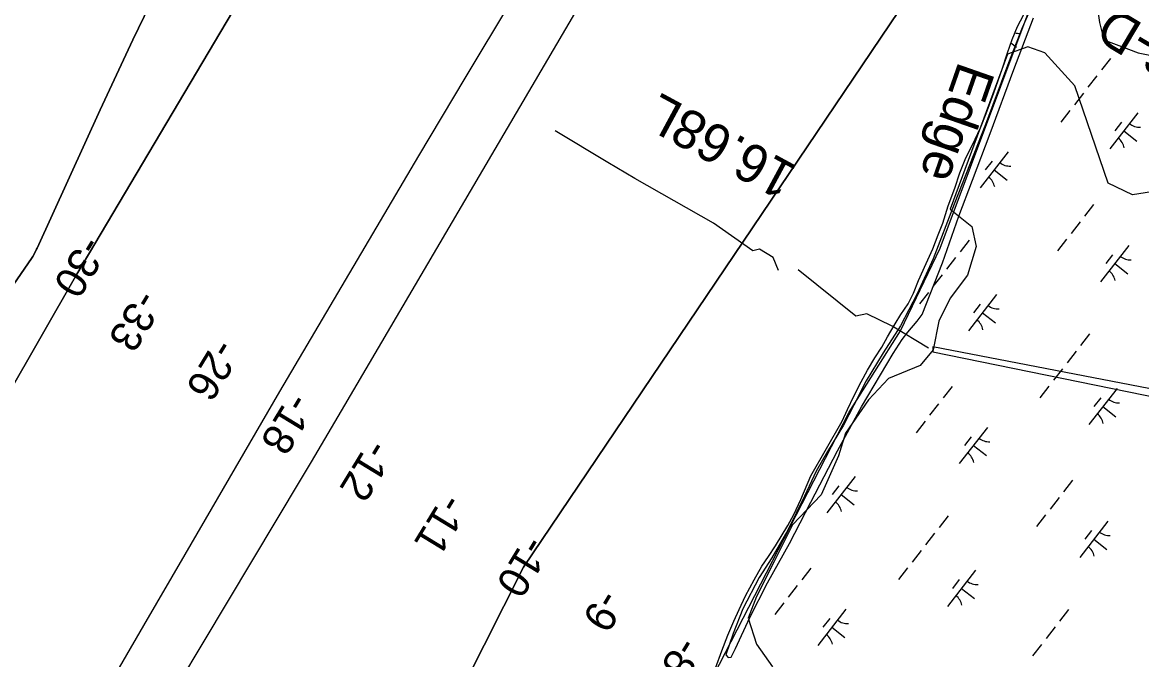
# Model space of a CAD drawing. Extents: x 3888273 to 3909528, y 158682 to 181032.
# Drawn here: x 3899572 to 3900792, y 167245 to 167939 of the extents above; entities that cross this region are included whole.
import ezdxf

# ---------------------------------------------------------------- set-up
doc = ezdxf.new("R2010")
doc.units = 0
for name, color, linetype in [('V-CHAN-DOCK', 7, 'Continuous'), ('V-LEVE-TOET', 7, 'Continuous'), ('V-RIVR-EDGE', 7, 'Continuous'), ('V-RIVR-IDEN', 7, 'Continuous'), ('V-RIVR-JETY', 7, 'Continuous'), ('V-RIVR-RANG', 7, 'Continuous'), ('V-RIVR-RANG-IDEN', 7, 'Continuous'), ('V-RRAP-FSHR', 7, 'Continuous'), ('V-STRM-FMON', 7, 'Continuous'), ('V-TOPO-DPTH', 7, 'Continuous'), ('V-TOPO-MINR', 7, 'Continuous'), ('V-WETL-SWMP', 7, 'Continuous')]:
    doc.layers.add(name, color=color, linetype=linetype)

msp = doc.modelspace()

# ---------------------------------------------------------------- linework, layer by layer
at = {"layer": 'V-CHAN-DOCK'}
msp.add_lwpolyline([(3900564.1, 167580.3), (3900918.3, 167508), (3900990.6, 167467.8), (3900997.5, 167477.5), (3900923.9, 167516.4), (3900564.1, 167585.8)], close=True, dxfattribs=at)
at = {"layer": 'V-LEVE-TOET'}
for points in [[(3900396, 167669), (3900390.1, 167683.2), (3900375.1, 167692.2), (3900367.9, 167690.4), (3900324.9, 167720.5), (3900239.4, 167769.3), (3900209.7, 167786.4), (3900152.6, 167821.2)], [(3900559.5, 167584.5), (3900519.7, 167608.3), (3900492.3, 167621.7), (3900480.3, 167619.3), (3900417.2, 167669.8)]]:
    msp.add_lwpolyline(points, dxfattribs=at)
at = {"layer": 'V-RIVR-EDGE'}
for points in [[(3900742.5, 167962.4), (3900745.6, 167938.9), (3900750.3, 167920.2), (3900787.8, 167906.1), (3900819.1, 167899.9)], [(3900811.3, 167756.1), (3900781.6, 167751.4), (3900755, 167763.9), (3900719, 167870.2), (3900686.2, 167906.1), (3900667.5, 167912.4), (3900645.6, 167904.6), (3900583.1, 167735.7), (3900606.5, 167717), (3900611.2, 167695.1), (3900601.8, 167663.8), (3900583.1, 167638.8), (3900570.6, 167613.8), (3900564.3, 167582.6), (3900550.2, 167565.4), (3900515.8, 167551.3), (3900494, 167527.9), (3900469, 167491.9), (3900461.1, 167466.9), (3900442.4, 167424.7), (3900411.1, 167391.9), (3900390.8, 167351.2), (3900372, 167313.7), (3900362.7, 167290.3), (3900372, 167262.1), (3900389.2, 167237.1)]]:
    msp.add_lwpolyline(points, dxfattribs=at)
at = {"layer": 'V-RIVR-JETY'}
for points in [[(3900678.9, 167973.2), (3900661.4, 167933.3), (3900646.5, 167895.2), (3900621.5, 167828.1), (3900587.3, 167741.2), (3900564.5, 167681.8), (3900546.8, 167643.6), (3900528.8, 167608.6), (3900509.9, 167579.1), (3900491.5, 167548.8), (3900477.8, 167522.3), (3900466.6, 167500.5), (3900449.1, 167471.8), (3900436.9, 167450.4), (3900424.2, 167423.2), (3900406, 167386), (3900388.7, 167356), (3900374.9, 167334.4), (3900357.1, 167300.3), (3900346.3, 167273.6), (3900338.5, 167250.4), (3900341, 167247.4), (3900344.2, 167247.8), (3900349, 167257.3), (3900364.6, 167291.1), (3900383.9, 167328.8), (3900407.8, 167371.7), (3900431.1, 167416.5), (3900460.2, 167472.4), (3900486.2, 167520.5), (3900521, 167578.4), (3900530.6, 167593.7), (3900536.7, 167601.7), (3900546.9, 167613.7), (3900552.5, 167620.9)], [(3900552.5, 167620.9), (3900574.6, 167677.3), (3900592.4, 167728), (3900607.4, 167767.5), (3900626.5, 167818.2), (3900652.2, 167887.9), (3900673.8, 167944.1)]]:
    msp.add_lwpolyline(points, dxfattribs=at)
at = {"layer": 'V-RRAP-FSHR'}
msp.add_lwpolyline([(3899996.7, 166588.8), (3900029.7, 166643.4), (3900051.8, 166695.8), (3900145, 166878), (3900473, 167514.6), (3900528.8, 167603.3), (3900571.9, 167693.2), (3900769.5, 168220.1), (3900854, 168410.1), (3901111.7, 168921.3), (3901230.8, 169130.1), (3901232.3, 169133), (3901298.6, 169231.8), (3901395, 169369.5), (3901586, 169601.1), (3901720.2, 169757.4), (3901855.1, 169965.2), (3902076, 170299.4), (3902258.6, 170576), (3902394.3, 170771.7), (3902466.4, 170877.4)], dxfattribs=at)
at = {"layer": 'V-TOPO-DPTH'}
for points in [[(3899237.6, 166978.5), (3899631, 167664.9), (3900022.2, 168324.2), (3900029.7, 168336.7), (3900037.2, 168349.1), (3900044.8, 168361.5), (3900052.5, 168373.8), (3900093.7, 168439.4), (3900122.1, 168484.4), (3900150.6, 168529.3), (3900179.4, 168574.1), (3900208.3, 168618.8), (3900453.3, 168995.5), (3900462.4, 169009.6), (3900471.5, 169023.7), (3900480.5, 169037.8), (3900489.5, 169051.9), (3900498.5, 169066.1), (3900507.4, 169080.2), (3900516.3, 169094.4), (3900525.2, 169108.6), (3900898, 169705.4)], [(3901523.7, 169550.8), (3901139.1, 169059.9), (3900979.7, 168809.1), (3900964.5, 168784.3), (3900949.7, 168759.3), (3900935.7, 168733.8), (3900922.2, 168708), (3900577.1, 168026.2), (3900117.9, 167345.7), (3899775.5, 166667.7), (3899771.7, 166626.4)], [(3900523.2, 169023), (3900524.6, 169025.3), (3900491.3, 169054.7), (3900490, 169052.7), (3900489.5, 169051.9), (3900480.5, 169037.8), (3900471.5, 169023.7), (3900462.4, 169009.6), (3900453.3, 168995.5), (3900208.3, 168618.8), (3900179.4, 168574.1), (3900150.6, 168529.3), (3900122.1, 168484.4), (3900093.7, 168439.4), (3900052.5, 168373.8), (3900044.8, 168361.5), (3900037.2, 168349.1), (3900029.7, 168336.7), (3900022.2, 168324.2), (3899631, 167664.9), (3899237.6, 166978.5), (3899234.6, 166973.7), (3899231.7, 166968.9), (3898895.1, 166384.7)], [(3899728.7, 167995.9), (3899692.2, 167920.1), (3899656.5, 167843.9), (3899587.8, 167693.4), (3899587.2, 167692), (3899585.4, 167688.1), (3899583.3, 167684.2), (3899582.5, 167683), (3899363.4, 167365)], [(3899363.4, 167365), (3899582.5, 167683), (3899583.3, 167684.2), (3899585.4, 167688.1), (3899587.2, 167692), (3899587.8, 167693.4), (3899656.5, 167843.9), (3899692.2, 167920.1), (3899728.7, 167995.9)], [(3899569, 167049.4), (3899614, 167127), (3899658.9, 167204.6), (3899704, 167282.1), (3899749, 167359.7), (3899826.1, 167492.2), (3899832.6, 167503.5), (3899839.2, 167514.7), (3899845.8, 167525.9), (3899852.4, 167537.1), (3899953.6, 167708.8), (3900003.9, 167793.7), (3900054.5, 167878.4), (3900105.3, 167962.9)], [(3899569, 167049.4), (3899614, 167127), (3899658.9, 167204.6), (3899704, 167282.1), (3899749, 167359.7), (3899826.1, 167492.2), (3899832.6, 167503.5), (3899839.2, 167514.7), (3899845.8, 167525.9), (3899852.4, 167537.1), (3899953.6, 167708.8), (3900003.9, 167793.7), (3900054.5, 167878.4), (3900105.3, 167962.9)]]:
    msp.add_lwpolyline(points, dxfattribs=at)
at = {"layer": 'V-TOPO-MINR'}
for points in [[(3899237.6, 166978.5), (3899631, 167664.9), (3900022.2, 168324.2), (3900029.7, 168336.7), (3900037.2, 168349.1), (3900044.8, 168361.5), (3900052.5, 168373.8), (3900093.7, 168439.4), (3900122.1, 168484.4), (3900150.6, 168529.3), (3900179.4, 168574.1), (3900208.3, 168618.8), (3900453.3, 168995.5), (3900462.4, 169009.6), (3900471.5, 169023.7), (3900480.5, 169037.8), (3900489.5, 169051.9), (3900498.5, 169066.1), (3900507.4, 169080.2), (3900516.3, 169094.4), (3900525.2, 169108.6), (3900898, 169705.4)], [(3899771.7, 166626.4), (3899775.5, 166667.7), (3900117.9, 167345.7), (3900577.1, 168026.2), (3900922.2, 168708), (3900935.7, 168733.8), (3900949.7, 168759.3), (3900964.5, 168784.3), (3900979.7, 168809.1), (3901139.1, 169059.9), (3901523.7, 169550.8)], [(3899571, 166932.8), (3899592.3, 166968.6), (3899613.6, 167004.4), (3899635, 167040.2), (3899876, 167442.3), (3899887, 167460.7), (3899897.9, 167479.1), (3899908.8, 167497.5), (3899919.7, 167516), (3900204.3, 168001.3)], [(3899363.4, 167365), (3899582.5, 167683), (3899583.3, 167684.2), (3899585.4, 167688.1), (3899587.2, 167692), (3899587.8, 167693.4), (3899656.5, 167843.9), (3899692.2, 167920.1), (3899728.7, 167995.9)], [(3899569, 167049.4), (3899614, 167127), (3899658.9, 167204.6), (3899704, 167282.1), (3899749, 167359.7), (3899826.1, 167492.2), (3899832.6, 167503.5), (3899839.2, 167514.7), (3899845.8, 167525.9), (3899852.4, 167537.1), (3899953.6, 167708.8), (3900003.9, 167793.7), (3900054.5, 167878.4), (3900105.3, 167962.9)]]:
    msp.add_lwpolyline(points, dxfattribs=at)
at = {"layer": 'V-WETL-SWMP'}
for p, q in [((3900656.4, 167934.6), (3900666.6, 167953.9)), ((3900650.5, 167920.7), (3900656.4, 167934.6)), ((3900645.3, 167906), (3900650.5, 167920.7)), ((3900649.1, 167916.8), (3900655.2, 167912.1)), ((3900639.7, 167888.3), (3900645.3, 167906)), ((3900757.7, 167900), (3900747.8, 167887.4)), ((3900635.3, 167876), (3900639.7, 167888.3)), ((3900742.9, 167881.1), (3900733.1, 167868.5)), ((3900630.5, 167862.5), (3900635.3, 167876)), ((3900622.3, 167840.1), (3900630.5, 167862.5)), ((3900728.2, 167862.1), (3900718.4, 167849.5)), ((3900713.4, 167843.2), (3900703.6, 167830.6)), ((3900616, 167824.3), (3900622.3, 167840.1)), ((3900787.6, 167840.7), (3900756.9, 167801.3)), ((3900607.4, 167805.8), (3900616, 167824.3)), ((3900769.8, 167830.5), (3900762.5, 167821)), ((3900772.2, 167821), (3900786.4, 167809.9)), ((3900600.2, 167791.8), (3900607.4, 167805.8)), ((3900646.3, 167798.3), (3900615.6, 167758.8)), ((3900593.5, 167775.3), (3900600.2, 167791.8)), ((3900628.6, 167788), (3900621.2, 167778.5)), ((3900588, 167758.7), (3900593.5, 167775.3)), ((3900631, 167778.5), (3900645.2, 167767.5)), ((3900580.9, 167739.4), (3900588, 167758.7)), ((3900575, 167720.5), (3900580.9, 167739.4)), ((3900739.3, 167740.8), (3900729.4, 167728.2)), ((3900724.5, 167721.9), (3900714.7, 167709.2)), ((3900569.8, 167707.8), (3900575, 167720.5)), ((3900563.9, 167692.4), (3900569.8, 167707.8)), ((3900603.5, 167702), (3900593.7, 167689.3)), ((3900709.8, 167702.9), (3900700, 167690.3)), ((3900556.8, 167676.6), (3900563.9, 167692.4)), ((3900777.6, 167696.1), (3900746.9, 167656.7)), ((3900759.9, 167685.9), (3900752.5, 167676.4)), ((3900548.6, 167658), (3900556.8, 167676.6)), ((3900588.8, 167683), (3900579, 167670.4)), ((3900762.3, 167676.4), (3900776.5, 167665.3)), ((3900574.1, 167664.1), (3900564.2, 167651.4)), ((3900543, 167644.1), (3900548.6, 167658)), ((3900537, 167632.6), (3900543, 167644.1)), ((3900559.3, 167645.1), (3900549.5, 167632.5)), ((3900633.5, 167642.7), (3900602.8, 167603.2)), ((3900529.1, 167620.9), (3900537, 167632.6)), ((3900615.7, 167632.4), (3900608.4, 167622.9)), ((3900523.1, 167610.9), (3900529.1, 167620.9)), ((3900618.1, 167622.9), (3900632.3, 167611.9)), ((3900514.8, 167596.6), (3900523.1, 167610.9)), ((3900734.8, 167599.8), (3900725, 167587.2)), ((3900508.4, 167585.4), (3900514.8, 167596.6)), ((3900500.9, 167573.8), (3900508.4, 167585.4)), ((3900720.1, 167580.9), (3900710.3, 167568.2)), ((3900493, 167560.2), (3900500.9, 167573.8)), ((3900485.8, 167547.5), (3900493, 167560.2)), ((3900705.4, 167561.9), (3900695.5, 167549.3)), ((3900478, 167532), (3900485.8, 167547.5)), ((3900585.2, 167542.7), (3900575.3, 167530.1)), ((3900690.6, 167543), (3900680.8, 167530.4)), ((3900764.8, 167540.5), (3900734.1, 167501.1)), ((3900470.9, 167517.4), (3900478, 167532)), ((3900747, 167530.3), (3900739.6, 167520.8)), ((3900465.3, 167505), (3900470.9, 167517.4)), ((3900570.4, 167523.8), (3900560.6, 167511.2)), ((3900749.4, 167520.8), (3900763.6, 167509.7)), ((3900431.1, 167445.1), (3900465.3, 167505)), ((3900555.7, 167504.9), (3900545.9, 167492.2)), ((3900623.5, 167498.1), (3900592.8, 167458.6)), ((3900605.8, 167487.8), (3900598.4, 167478.3)), ((3900608.2, 167478.3), (3900622.4, 167467.3)), ((3900420.3, 167419.6), (3900431.1, 167445.1)), ((3900479.4, 167444.6), (3900448.7, 167405.1)), ((3900716.4, 167440.6), (3900706.6, 167428)), ((3900461.6, 167434.3), (3900454.2, 167424.9)), ((3900412.4, 167403), (3900420.3, 167419.6)), ((3900464, 167424.9), (3900478.2, 167413.8)), ((3900701.7, 167421.7), (3900691.9, 167409)), ((3900406, 167391.1), (3900412.4, 167403)), ((3900580.7, 167401.8), (3900570.9, 167389.1)), ((3900687, 167402.7), (3900677.1, 167390.1)), ((3900754.8, 167395.9), (3900724.1, 167356.5)), ((3900392.5, 167369), (3900406, 167391.1)), ((3900566, 167382.8), (3900556.2, 167370.2)), ((3900737, 167385.7), (3900729.7, 167376.2)), ((3900385, 167357.4), (3900392.5, 167369)), ((3900739.4, 167376.2), (3900753.7, 167365.1)), ((3900377.8, 167346.9), (3900385, 167357.4)), ((3900551.2, 167363.9), (3900541.4, 167351.2)), ((3900369.2, 167331.9), (3900377.8, 167346.9)), ((3900431, 167344.7), (3900421.2, 167332.1)), ((3900536.5, 167344.9), (3900526.7, 167332.3)), ((3900359.8, 167314.5), (3900369.2, 167331.9)), ((3900610.7, 167342.5), (3900579.9, 167303)), ((3900592.9, 167332.2), (3900585.5, 167322.7)), ((3900416.3, 167325.7), (3900406.5, 167313.1)), ((3900595.3, 167322.7), (3900609.5, 167311.7)), ((3900353.1, 167299.8), (3900359.8, 167314.5)), ((3900401.6, 167306.8), (3900391.7, 167294.2)), ((3900347.1, 167287.1), (3900353.1, 167299.8)), ((3900469.4, 167300), (3900438.7, 167260.5)), ((3900712, 167299.6), (3900702.2, 167287)), ((3900340.7, 167271.6), (3900347.1, 167287.1)), ((3900451.7, 167289.7), (3900444.3, 167280.3)), ((3900334, 167254.7), (3900340.7, 167271.6)), ((3900454.1, 167280.3), (3900468.3, 167269.2)), ((3900697.3, 167280.7), (3900687.4, 167268)), ((3900682.5, 167261.7), (3900672.7, 167249.1)), ((3900327, 167235.8), (3900334, 167254.7))]:
    msp.add_line(p, q, dxfattribs=at)
for centre, start, end in [((3900658.1, 167944.8), 254.9283, 272.8866), ((3900789.4, 167842.6), 231.343, 272.8866), ((3900755.5, 167799), 11.343, 52.8866), ((3900648.1, 167800.2), 231.343, 272.8866), ((3900614.2, 167756.6), 11.343, 52.8866), ((3900779.4, 167698.1), 231.343, 272.8866), ((3900745.5, 167654.5), 11.343, 52.8866), ((3900635.3, 167644.6), 231.343, 272.8866), ((3900601.4, 167601), 11.343, 52.8866), ((3900766.6, 167542.4), 231.343, 272.8866), ((3900732.6, 167498.8), 11.343, 52.8866), ((3900625.3, 167500), 231.343, 272.8866), ((3900591.4, 167456.4), 11.343, 52.8866), ((3900481.2, 167446.5), 231.343, 272.8866), ((3900447.2, 167402.9), 11.343, 52.8866), ((3900756.6, 167397.8), 231.343, 272.8866), ((3900722.7, 167354.2), 11.343, 52.8866), ((3900612.4, 167344.4), 231.343, 272.8866), ((3900578.5, 167300.8), 11.343, 52.8866), ((3900471.2, 167301.9), 231.343, 272.8866), ((3900437.3, 167258.3), 11.343, 52.8866)]:
    msp.add_arc(centre, 17.6, start, end, dxfattribs=at)

# ---------------------------------------------------------------- texts
at = {"layer": 'V-RIVR-IDEN'}
msp.add_text('Edge', height=42, rotation=250.7537, dxfattribs=at).set_placement((3900592.6, 167898))
at = {"layer": 'V-RIVR-RANG'}
for s, rotation, p in [('-30', 238.7803, (3899638.1, 167709)), ('-33', 238.6383, (3899698.2, 167650)), ('-26', 238.6383, (3899782.8, 167596.6)), ('-18', 238.6383, (3899864, 167537.8)), ('-12', 238.6383, (3899950.1, 167486.8)), ('-11', 238.6383, (3900031.3, 167427.9)), ('-10', 238.6383, (3900120.7, 167382.4)), ('-9', 238.6383, (3900201.9, 167323.6)), ('-8', 238.6383, (3900287.7, 167272.1))]:
    msp.add_text(s, height=33.5, rotation=rotation, dxfattribs=at).set_placement(p)
at = {"layer": 'V-RIVR-RANG-IDEN'}
msp.add_text('R-36-D', height=41.5, rotation=149.1858, dxfattribs=at).set_placement((3900913.9, 167865.6))
at = {"layer": 'V-STRM-FMON'}
msp.add_text('16.68L', height=42, rotation=151.5808, dxfattribs=at).set_placement((3900418.2, 167781.4))

doc.saveas('drawing.dxf')
